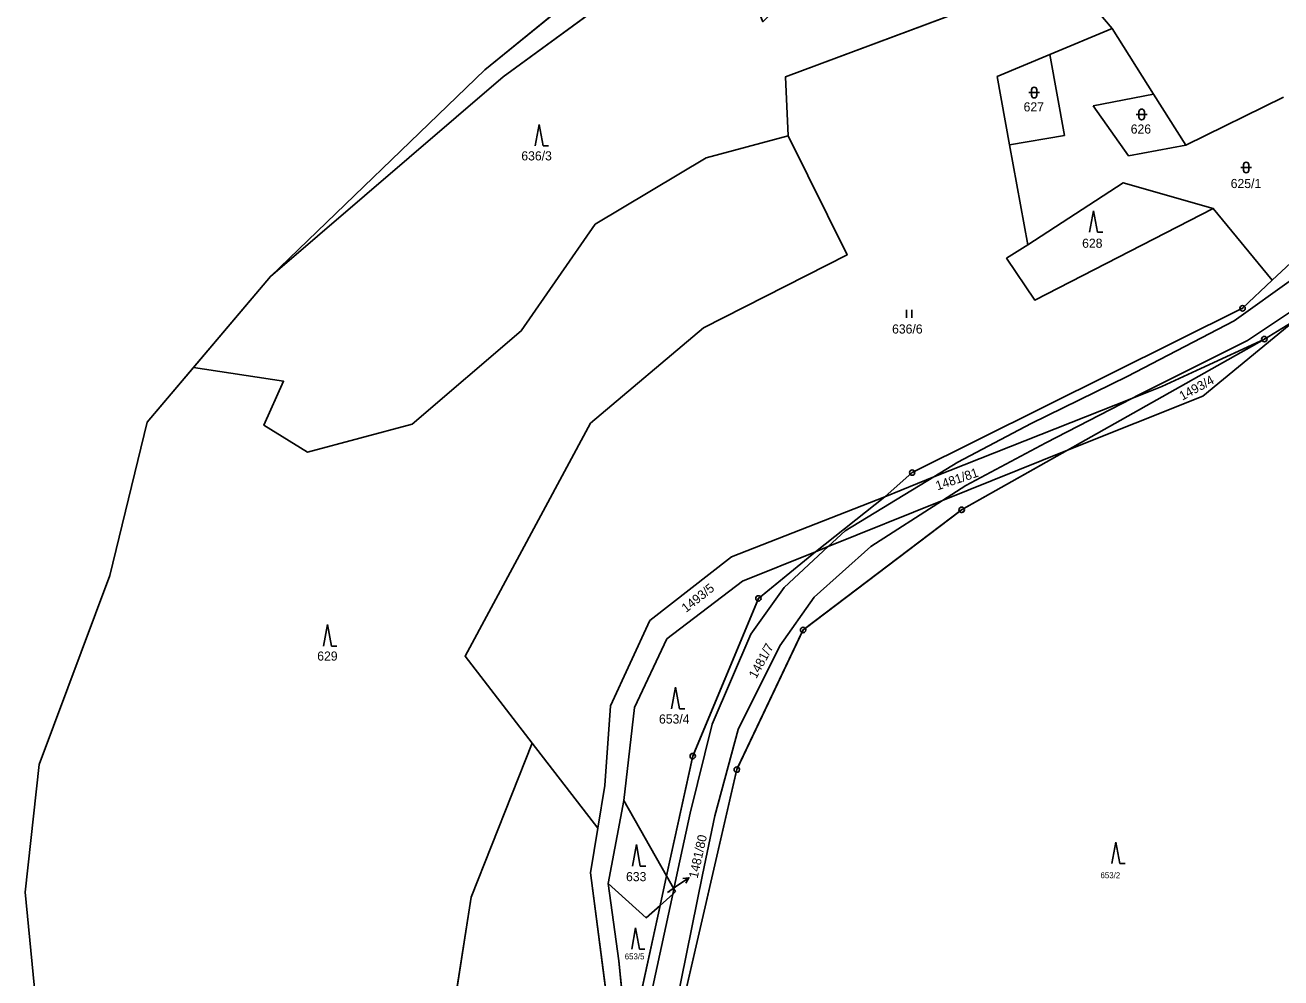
# Model space of a CAD drawing. Extents: x -760642 to -757221, y -1092371 to -1088855.
# Drawn here: x -760311.9 to -760077.8, y -1090669.8 to -1090492.3 of the extents above; entities that cross this region are included whole.
import ezdxf

# ---------------------------------------------------------------- set-up
doc = ezdxf.new("R2010")
doc.units = 0
for name, color, linetype in [('Vrstva 1', 7, 'Continuous'), ('Vrstva 13', 7, 'Continuous'), ('Vrstva 16', 7, 'Continuous'), ('Vrstva 18', 7, 'Continuous'), ('Vrstva 24', 7, 'Continuous'), ('Vrstva 25', 7, 'Continuous'), ('Vrstva 28', 7, 'Continuous'), ('Vrstva 30', 7, 'Continuous'), ('Vrstva 4', 7, 'Continuous')]:
    doc.layers.add(name, color=color, linetype=linetype)

msp = doc.modelspace()

# ---------------------------------------------------------------- linework, layer by layer
at = {"layer": 'Vrstva 1'}
for p, q in [((-760186.3, -1090475.22), (-760222.79, -1090501.97)), ((-760118.12, -1090482.53), (-760170.2, -1090501.96)), ((-760118.12, -1090482.53), (-760109.25, -1090492.94)), ((-760109.25, -1090492.94), (-760120.89, -1090497.77)), ((-760101.55, -1090505.18), (-760109.25, -1090492.94)), ((-760120.89, -1090497.77), (-760130.74, -1090501.86)), ((-760118.18, -1090512.87), (-760120.89, -1090497.77)), ((-760222.79, -1090501.97), (-760266.18, -1090539.15)), ((-760170.2, -1090501.96), (-760169.67, -1090512.92)), ((-760130.74, -1090501.86), (-760128.41, -1090514.64)), ((-760101.55, -1090505.18), (-760112.8, -1090507.34)), ((-760095.56, -1090514.7), (-760101.55, -1090505.18)), ((-760112.8, -1090507.34), (-760106.23, -1090516.65)), ((-760077.32, -1090505.75), (-760095.56, -1090514.7)), ((-760184.95, -1090517.02), (-760169.67, -1090512.92)), ((-760169.67, -1090512.92), (-760158.69, -1090535.14)), ((-760128.41, -1090514.64), (-760118.18, -1090512.87)), ((-760128.41, -1090514.64), (-760125.02, -1090533.22)), ((-760205.65, -1090529.42), (-760184.95, -1090517.02)), ((-760106.23, -1090516.65), (-760095.56, -1090514.7)), ((-760107.2, -1090521.67), (-760125.02, -1090533.22)), ((-760107.2, -1090521.67), (-760090.43, -1090526.49)), ((-760063.02, -1090524.4), (-760079.42, -1090539.86)), ((-760123.71, -1090543.53), (-760090.43, -1090526.49)), ((-760090.43, -1090526.49), (-760079.42, -1090539.86)), ((-760219.44, -1090549.29), (-760205.65, -1090529.42)), ((-760125.02, -1090533.22), (-760128.95, -1090535.76)), ((-760158.69, -1090535.14), (-760185.48, -1090548.74)), ((-760128.95, -1090535.76), (-760123.71, -1090543.53)), ((-760079.42, -1090539.86), (-760084.96, -1090545.08)), ((-760146.56, -1090575.69), (-760084.96, -1090545.08)), ((-760092.34, -1090561.46), (-760075.22, -1090547.37)), ((-760080.9, -1090550.82), (-760075.22, -1090547.37)), ((-760239.8, -1090566.67), (-760219.44, -1090549.29)), ((-760185.48, -1090548.74), (-760206.53, -1090566.51)), ((-760117.6, -1090571.5), (-760080.9, -1090550.82)), ((-760080.9, -1090550.82), (-760092.76, -1090556.31)), ((-760280.55, -1090556.13), (-760263.75, -1090558.66)), ((-760092.76, -1090556.31), (-760099.99, -1090559.66)), ((-760263.75, -1090558.66), (-760267.4, -1090566.86)), ((-760117.6, -1090571.5), (-760092.34, -1090561.46)), ((-760099.99, -1090559.66), (-760105.58, -1090561.87)), ((-760105.58, -1090561.87), (-760142.54, -1090576.48)), ((-760267.4, -1090566.86), (-760259.29, -1090571.88)), ((-760259.29, -1090571.88), (-760239.8, -1090566.67)), ((-760206.53, -1090566.51), (-760229.91, -1090609.89)), ((-760140.9, -1090580.89), (-760117.6, -1090571.5)), ((-760137.33, -1090582.62), (-760117.6, -1090571.5)), ((-760146.56, -1090575.69), (-760151.63, -1090580.18)), ((-760142.54, -1090576.48), (-760151.63, -1090580.18)), ((-760151.63, -1090580.18), (-760180.22, -1090591.37)), ((-760151.63, -1090580.18), (-760164.58, -1090590.44)), ((-760162.2, -1090589.48), (-760140.9, -1090580.89)), ((-760166.89, -1090605.02), (-760137.33, -1090582.62)), ((-760164.58, -1090590.44), (-760162.2, -1090589.48)), ((-760180.22, -1090591.37), (-760195.44, -1090603.24)), ((-760178.21, -1090595.93), (-760164.58, -1090590.44)), ((-760164.58, -1090590.44), (-760175.22, -1090599.14)), ((-760178.21, -1090595.93), (-760192.3, -1090606.69)), ((-760175.22, -1090599.14), (-760187.47, -1090628.52)), ((-760195.44, -1090603.24), (-760202.82, -1090619.16)), ((-760179.25, -1090631.04), (-760166.89, -1090605.02)), ((-760192.3, -1090606.69), (-760198.33, -1090619.44)), ((-760229.91, -1090609.89), (-760217.38, -1090626.14)), ((-760202.82, -1090619.16), (-760203.85, -1090634)), ((-760198.33, -1090619.44), (-760200.31, -1090636.79)), ((-760217.38, -1090626.14), (-760228.75, -1090654.79)), ((-760217.38, -1090626.14), (-760205.17, -1090641.97)), ((-760187.47, -1090628.52), (-760192.34, -1090650.83)), ((-760197.15, -1090708.68), (-760179.25, -1090631.04)), ((-760203.85, -1090634), (-760205.17, -1090641.97)), ((-760200.31, -1090636.79), (-760203.21, -1090652.24)), ((-760200.31, -1090636.79), (-760192.34, -1090650.83)), ((-760205.17, -1090641.97), (-760206.55, -1090650.27)), ((-760206.55, -1090650.27), (-760203.22, -1090675.51)), ((-760203.21, -1090652.24), (-760201.22, -1090666.68)), ((-760196.12, -1090658.64), (-760203.21, -1090652.24)), ((-760192.34, -1090650.83), (-760193.54, -1090656.35)), ((-760192.34, -1090650.83), (-760190.97, -1090653.23)), ((-760228.75, -1090654.79), (-760233.03, -1090682.11)), ((-760191.19, -1090654.26), (-760193.54, -1090656.35)), ((-760190.66, -1090653.78), (-760191.19, -1090654.26)), ((-760190.97, -1090653.23), (-760190.66, -1090653.78)), ((-760193.54, -1090656.35), (-760199.55, -1090683.89)), ((-760193.54, -1090656.35), (-760196.12, -1090658.64)), ((-760201.22, -1090666.68), (-760199.55, -1090683.89))]:
    msp.add_line(p, q, dxfattribs=at)
at = {"layer": 'Vrstva 13'}
for p, q in [((-760226.22, -1090500.67), (-760185.77, -1090467.67)), ((-760266.18, -1090539.15), (-760226.22, -1090500.67)), ((-760266.18, -1090539.15), (-760280.55, -1090556.13)), ((-760280.55, -1090556.13), (-760289.17, -1090566.32)), ((-760296.15, -1090594.86), (-760289.17, -1090566.32)), ((-760309.34, -1090630.09), (-760296.15, -1090594.86)), ((-760311.93, -1090653.88), (-760309.34, -1090630.09)), ((-760311.93, -1090653.88), (-760309.98, -1090673.67))]:
    msp.add_line(p, q, dxfattribs=at)
at = {"layer": 'Vrstva 16'}
for p, q in [((-760190.65, -1090652.91), (-760188.187, -1090651.198)), ((-760192.16, -1090653.96), (-760190.65, -1090652.91))]:
    msp.add_line(p, q, dxfattribs=at)
msp.add_lwpolyline([(-760189.293, -1090651.358), (-760188.187, -1090651.198), (-760188.722, -1090652.179)], dxfattribs=at)
at = {"layer": 'Vrstva 24'}
for centre, radius in [((-760084.96, -1090545.08), 0.5), ((-760084.96, -1090545.08), 0.0327), ((-760080.9, -1090550.82), 0.5), ((-760080.9, -1090550.82), 0.0327), ((-760146.56, -1090575.69), 0.5), ((-760146.56, -1090575.69), 0.0327), ((-760137.33, -1090582.62), 0.5), ((-760137.33, -1090582.62), 0.0327), ((-760175.22, -1090599.14), 0.5), ((-760175.22, -1090599.14), 0.0327), ((-760166.89, -1090605.02), 0.5), ((-760166.89, -1090605.02), 0.0327), ((-760187.47, -1090628.52), 0.5), ((-760187.47, -1090628.52), 0.0327), ((-760179.25, -1090631.04), 0.5), ((-760179.25, -1090631.04), 0.0327)]:
    msp.add_circle(centre, radius, dxfattribs=at)
at = {"layer": 'Vrstva 25'}
for p, q in [((-760124.81, -1090504.87), (-760122.81, -1090504.87)), ((-760124.31, -1090505.37), (-760124.31, -1090504.37)), ((-760123.31, -1090505.37), (-760123.31, -1090504.37)), ((-760104.77, -1090508.96), (-760102.77, -1090508.96)), ((-760104.27, -1090509.46), (-760104.27, -1090508.46)), ((-760103.27, -1090509.46), (-760103.27, -1090508.46)), ((-760216.102, -1090510.809), (-760216.835, -1090514.809)), ((-760216.102, -1090510.809), (-760215.369, -1090514.809)), ((-760215.369, -1090514.809), (-760214.369, -1090514.809)), ((-760085.29, -1090518.84), (-760083.29, -1090518.84)), ((-760084.79, -1090519.34), (-760084.79, -1090518.34)), ((-760083.79, -1090519.34), (-760083.79, -1090518.34)), ((-760112.762, -1090526.919), (-760113.495, -1090530.919)), ((-760112.762, -1090526.919), (-760112.029, -1090530.919)), ((-760112.029, -1090530.919), (-760111.029, -1090530.919)), ((-760147.617, -1090545.345), (-760147.617, -1090546.845)), ((-760146.595, -1090546.845), (-760146.595, -1090545.345)), ((-760255.542, -1090604.019), (-760256.275, -1090608.019)), ((-760255.542, -1090604.019), (-760254.809, -1090608.019)), ((-760254.809, -1090608.019), (-760253.809, -1090608.019)), ((-760190.672, -1090615.689), (-760191.405, -1090619.689)), ((-760190.672, -1090615.689), (-760189.939, -1090619.689)), ((-760189.939, -1090619.689), (-760188.939, -1090619.689)), ((-760197.972, -1090645.019), (-760198.705, -1090649.019)), ((-760197.972, -1090645.019), (-760197.239, -1090649.019)), ((-760108.602, -1090644.559), (-760109.335, -1090648.559)), ((-760108.602, -1090644.559), (-760107.869, -1090648.559)), ((-760197.239, -1090649.019), (-760196.239, -1090649.019)), ((-760107.869, -1090648.559), (-760106.869, -1090648.559)), ((-760198.112, -1090660.499), (-760198.845, -1090664.499)), ((-760198.112, -1090660.499), (-760197.379, -1090664.499)), ((-760197.379, -1090664.499), (-760196.379, -1090664.499))]:
    msp.add_line(p, q, dxfattribs=at)
for centre, start, end in [((-760123.81, -1090504.37), 0, 180), ((-760123.81, -1090505.37), 180, 0), ((-760103.77, -1090508.46), 0, 180), ((-760103.77, -1090509.46), 180, 0), ((-760084.29, -1090518.34), 0, 180), ((-760084.29, -1090519.34), 180, 0)]:
    msp.add_arc(centre, 0.5, start, end, dxfattribs=at)
at = {"layer": 'Vrstva 28'}
msp.add_lwpolyline([(-760309.98, -1090673.67), (-760311.93, -1090653.88), (-760309.34, -1090630.09), (-760296.15, -1090594.86), (-760289.17, -1090566.32), (-760266.18, -1090539.15), (-760226.22, -1090500.67), (-760185.77, -1090467.67)], dxfattribs=at)
at = {"layer": 'Vrstva 30'}
for points in [[(-760280.548, -1090556.13), (-760263.75, -1090558.66), (-760267.4, -1090566.86), (-760259.29, -1090571.88), (-760239.8, -1090566.67), (-760219.44, -1090549.29), (-760205.65, -1090529.42), (-760184.95, -1090517.02), (-760169.67, -1090512.92), (-760170.2, -1090501.96), (-760118.12, -1090482.53), (-760123.36, -1090466.8), (-760124.53, -1090442.24), (-760174.38, -1090491.68), (-760183.76, -1090468.62), (-760187.008, -1090460.042), (-760185.77, -1090467.67), (-760186.3, -1090475.22), (-760222.79, -1090501.97), (-760266.18, -1090539.15), (-760280.548, -1090556.13)], [(-760266.18, -1090539.15), (-760222.79, -1090501.97), (-760186.3, -1090475.22), (-760185.77, -1090467.67), (-760226.22, -1090500.67), (-760266.18, -1090539.15)], [(-760233.03, -1090682.11), (-760228.75, -1090654.79), (-760217.38, -1090626.14), (-760229.91, -1090609.89), (-760206.53, -1090566.51), (-760185.48, -1090548.74), (-760158.69, -1090535.14), (-760169.67, -1090512.92), (-760184.95, -1090517.02), (-760205.65, -1090529.42), (-760219.44, -1090549.29), (-760239.8, -1090566.67), (-760259.29, -1090571.88), (-760267.4, -1090566.86), (-760263.75, -1090558.66), (-760280.548, -1090556.13)], [(-760125.02, -1090533.22), (-760128.95, -1090535.76), (-760123.71, -1090543.53), (-760090.43, -1090526.49), (-760107.2, -1090521.67), (-760125.02, -1090533.22)], [(-760075.22, -1090547.37), (-760092.34, -1090561.46), (-760117.6, -1090571.5), (-760136.894, -1090582.375)], [(-760280.548, -1090556.13), (-760280.549, -1090556.131), (-760289.17, -1090566.32), (-760296.15, -1090594.86), (-760309.34, -1090630.09), (-760311.93, -1090653.88), (-760309.98, -1090673.67)], [(-760137.729, -1090582.922), (-760166.491, -1090604.718)], [(-760174.833, -1090598.823), (-760164.58, -1090590.44), (-760178.21, -1090595.93), (-760192.3, -1090606.69), (-760198.33, -1090619.44), (-760200.31, -1090636.79), (-760192.34, -1090650.83), (-760187.577, -1090629.008)], [(-760187.278, -1090628.059), (-760175.412, -1090599.601)], [(-760167.105, -1090605.472), (-760179.035, -1090630.588)], [(-760205.053, -1090709.111), (-760201.9, -1090694.66), (-760203.22, -1090675.51), (-760206.55, -1090650.27), (-760205.17, -1090641.97), (-760217.38, -1090626.14), (-760228.75, -1090654.79), (-760233.03, -1090682.11), (-760244.46, -1090691.17), (-760262.78, -1090673.01), (-760290.16, -1090697.58), (-760299.59, -1090751.55), (-760292.14, -1090767.45), (-760286.18, -1090784.42), (-760277.14, -1090810.8), (-760261.87, -1090840.05), (-760255.71, -1090849.28), (-760250.406, -1090841.68)], [(-760179.362, -1090631.527), (-760197.15, -1090708.68), (-760196.64, -1090713.4), (-760197.657, -1090715.711), (-760202.58, -1090726.9), (-760202.96, -1090728.08), (-760210.504, -1090749.473), (-760215.764, -1090764.388)], [(-760193.54, -1090656.35), (-760192.34, -1090650.83), (-760200.31, -1090636.79), (-760203.21, -1090652.24), (-760196.12, -1090658.64), (-760193.54, -1090656.35)], [(-760193.54, -1090656.35), (-760196.12, -1090658.64), (-760203.21, -1090652.24), (-760201.22, -1090666.68), (-760199.55, -1090683.89), (-760193.54, -1090656.35)]]:
    msp.add_lwpolyline(points, dxfattribs=at)
for centre, start, end in [((-760137.33, -1090582.62), 0, 29.40599), ((-760137.33, -1090582.62), 217.15415, 0), ((-760175.22, -1090599.14), 39.27181, 180), ((-760175.22, -1090599.14), 180, 247.36629), ((-760166.89, -1090605.02), 244.59138, 0), ((-760166.89, -1090605.02), 0, 37.15415), ((-760187.47, -1090628.52), 67.36629, 180), ((-760187.47, -1090628.52), 180, 257.68619), ((-760179.25, -1090631.04), 257.01724, 0), ((-760179.25, -1090631.04), 0, 64.59138)]:
    msp.add_arc(centre, 0.5, start, end, dxfattribs=at)
at = {"layer": 'Vrstva 4'}
for p, q in [((-760086.5, -1090547.43), (-760075.38, -1090539.44)), ((-760072.12, -1090543.1), (-760084.04, -1090551.07)), ((-760106.47, -1090557.78), (-760086.5, -1090547.43)), ((-760084.04, -1090551.07), (-760104.3, -1090561.21)), ((-760124.39, -1090566.52), (-760106.47, -1090557.78)), ((-760104.3, -1090561.21), (-760105.58, -1090561.87)), ((-760105.58, -1090561.87), (-760121.62, -1090570.14)), ((-760138.07, -1090573.75), (-760124.39, -1090566.52)), ((-760121.62, -1090570.14), (-760136.57, -1090578.11)), ((-760142.54, -1090576.48), (-760138.07, -1090573.75)), ((-760159.04, -1090586.55), (-760142.54, -1090576.48)), ((-760136.57, -1090578.11), (-760140.9, -1090580.89)), ((-760140.9, -1090580.89), (-760154.24, -1090589.47)), ((-760162.2, -1090589.48), (-760159.04, -1090586.55)), ((-760170.43, -1090597.12), (-760162.2, -1090589.48)), ((-760164.82, -1090598.89), (-760154.24, -1090589.47)), ((-760176.61, -1090605.8), (-760170.43, -1090597.12)), ((-760171.23, -1090607.98), (-760164.82, -1090598.89)), ((-760183.87, -1090622.6), (-760176.61, -1090605.8)), ((-760178.99, -1090623.55), (-760171.23, -1090607.98)), ((-760187.92, -1090639.17), (-760183.87, -1090622.6)), ((-760178.99, -1090623.55), (-760183.37, -1090639.63)), ((-760190.16, -1090649.48), (-760187.92, -1090639.17)), ((-760183.37, -1090639.63), (-760185.67, -1090650.63)), ((-760190.97, -1090653.23), (-760190.16, -1090649.48)), ((-760185.67, -1090650.63), (-760190.83, -1090676.08)), ((-760195.84, -1090675.67), (-760191.19, -1090654.26)), ((-760191.19, -1090654.26), (-760190.97, -1090653.23))]:
    msp.add_line(p, q, dxfattribs=at)

# ---------------------------------------------------------------- texts
at = {"layer": 'Vrstva 16'}
msp.add_text('1481/80', height=1.7, rotation=77.47119, dxfattribs=at).set_placement((-760186.57, -1090651.41))
at = {"layer": 'Vrstva 18'}
for s, height, p in [('627', 1.7, (-760125.78, -1090508.39)), ('626', 1.7, (-760105.81, -1090512.52)), ('636/3', 1.7, (-760219.42, -1090517.52)), ('625/1', 1.7, (-760087.17, -1090522.67)), ('628', 1.7, (-760114.87, -1090533.8)), ('636/6', 1.7, (-760150.3, -1090549.78)), ('629', 1.7, (-760257.469, -1090610.73)), ('653/4', 1.7, (-760193.757, -1090622.46)), ('633', 1.7, (-760199.898, -1090651.83)), ('653/2', 1.1, (-760111.448, -1090651.27)), ('1481/80', 0.1, (-760192.16, -1090653.96)), ('653/5', 1.1, (-760200.146, -1090666.4))]:
    msp.add_text(s, height=height, dxfattribs=at).set_placement(p)
for s, rotation, p in [('1493/4', 28.75077, (-760096.19, -1090562.31)), ('1481/81', 18.76806, (-760141.84, -1090579.02)), ('1493/5', 38.4642, (-760188.71, -1090601.86)), ('1481/7', 61.38954, (-760175.64, -1090614.22))]:
    msp.add_text(s, height=1.7, rotation=rotation, dxfattribs=at).set_placement(p)

doc.saveas('drawing.dxf')
